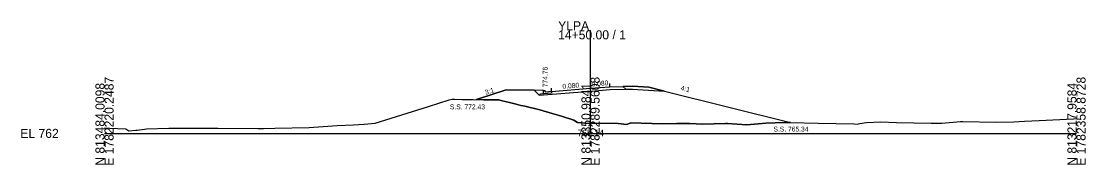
# Model space of a CAD drawing. Extents: x -76 to 1303, y -10 to 9544.
# Drawn here: x -25.7 to 302.8, y 4490.3 to 4534.7 of the extents above; entities that cross this region are included whole.
import ezdxf

# ---------------------------------------------------------------- set-up
doc = ezdxf.new("R2010")
doc.units = 0
for name, color, linetype in [('Exist Cross Section Cell', 7, 'Continuous'), ('Exist XS Center Line Elevation Label', 7, 'Continuous'), ('Exist XS Ground Line', 7, 'Continuous'), ('Prop XS Dump Level', 7, 'Continuous'), ('Prop XS Earthwork Shape', 7, 'Continuous'), ('Prop XS EOT Tick Mark', 7, 'Continuous'), ('Prop XS Finish Grade', 7, 'Continuous'), ('Prop XS Finish Grade CurbGutter', 7, 'Continuous'), ('Prop XS Finish Grade Earthwork', 7, 'Continuous'), ('Prop XS Finish Grade Paved Shoulder', 7, 'Continuous'), ('Prop XS Finish Grade Pavement', 7, 'Continuous'), ('Prop XS Hydro Elevations', 7, 'Continuous'), ('Prop XS Pvmt Edge Slope', 7, 'Continuous'), ('Prop XS SE Text', 7, 'Continuous'), ('Prop XS Side Slope Text', 7, 'Continuous'), ('Prop XS SS Elevation Text', 7, 'Continuous'), ('Prop XS Subgrade CurbGutter', 7, 'Continuous'), ('Prop XS Subgrade Earthwork', 7, 'Continuous'), ('Scratch_Level_3', 7, 'Continuous')]:
    doc.layers.add(name, color=color, linetype=linetype)

msp = doc.modelspace()

# ---------------------------------------------------------------- linework, layer by layer
at = {"layer": 'Exist Cross Section Cell'}
for p, q in [((150, 4500), (150, 4531.87)), ((0, 4500), (150, 4500)), ((150, 4500), (300, 4500))]:
    msp.add_line(p, q, dxfattribs=at)
at = {"layer": 'Exist XS Ground Line'}
for p, q in [((83.56, 4503.15), (99.98, 4508.29)), ((99.98, 4508.29), (106.4, 4510.34)), ((106.4, 4510.34), (107.28, 4510.62)), ((107.28, 4510.62), (108.01, 4510.59)), ((108.01, 4510.59), (110.34, 4510.51)), ((110.34, 4510.51), (111.4, 4510.46)), ((111.4, 4510.46), (113.79, 4510.43)), ((113.79, 4510.43), (117.1, 4510.42)), ((117.1, 4510.42), (121.68, 4510.41)), ((121.68, 4510.41), (122.76, 4510.04)), ((122.76, 4510.04), (123.61, 4509.86)), ((123.61, 4509.86), (125.37, 4509.44)), ((125.37, 4509.44), (127.06, 4509.03)), ((127.06, 4509.03), (128.45, 4508.67)), ((128.45, 4508.67), (129.7, 4508.41)), ((129.7, 4508.41), (134.36, 4507.31)), ((134.36, 4507.31), (138.19, 4506.11)), ((138.19, 4506.11), (141.05, 4505.32)), ((141.05, 4505.32), (144.8, 4504.04)), ((288.47, 4503.99), (299.1, 4504.49)), ((299.1, 4504.49), (300, 4504.57)), ((0, 4501.76), (1.49, 4501.64)), ((1.49, 4501.64), (6.55, 4501.43)), ((6.55, 4501.43), (7.5, 4500.84)), ((7.5, 4500.84), (9.69, 4500.96)), ((9.69, 4500.96), (10.1, 4500.99)), ((10.1, 4500.99), (12.3, 4501.32)), ((12.3, 4501.32), (12.99, 4501.36)), ((12.99, 4501.36), (19.89, 4501.66)), ((19.89, 4501.66), (20.56, 4501.66)), ((20.56, 4501.66), (34.98, 4501.63)), ((34.98, 4501.63), (47.37, 4501.51)), ((47.37, 4501.51), (49.07, 4501.5)), ((49.07, 4501.5), (52.52, 4501.58)), ((52.52, 4501.58), (63.12, 4501.82)), ((63.12, 4501.82), (71.85, 4502.39)), ((71.85, 4502.39), (76.8, 4502.67)), ((76.8, 4502.67), (80.16, 4502.83)), ((80.16, 4502.83), (83.56, 4503.15)), ((144.8, 4504.04), (145.96, 4503.32)), ((145.96, 4503.32), (149.33, 4503.07)), ((149.33, 4503.07), (150.28, 4503.16)), ((150.28, 4503.16), (158.49, 4503.06)), ((158.49, 4503.06), (161.17, 4502.75)), ((161.17, 4502.75), (162.4, 4503.27)), ((162.4, 4503.27), (172.16, 4502.99)), ((172.16, 4502.99), (176.6, 4503.05)), ((176.6, 4503.05), (180.58, 4503.05)), ((180.58, 4503.05), (184.63, 4502.8)), ((184.63, 4502.8), (191.64, 4503.03)), ((191.64, 4503.03), (192.27, 4503.06)), ((192.27, 4503.06), (198.26, 4502.65)), ((198.26, 4502.65), (204.12, 4503.11)), ((204.12, 4503.11), (209.84, 4503.32)), ((209.84, 4503.32), (210.87, 4503.32)), ((210.87, 4503.32), (211.7, 4503.34)), ((211.7, 4503.34), (220.26, 4503.12)), ((220.26, 4503.12), (231.31, 4502.94)), ((231.31, 4502.94), (232.26, 4502.9)), ((232.26, 4502.9), (233.15, 4503.04)), ((233.15, 4503.04), (235.13, 4503.35)), ((235.13, 4503.35), (239.63, 4503.58)), ((239.63, 4503.58), (244.4, 4503.41)), ((244.4, 4503.41), (255.16, 4503.12)), ((255.16, 4503.12), (256.57, 4503.13)), ((256.57, 4503.13), (256.97, 4503.17)), ((256.97, 4503.17), (258.43, 4503.17)), ((258.43, 4503.17), (264.2, 4503.66)), ((264.2, 4503.66), (264.94, 4503.67)), ((264.94, 4503.67), (275.13, 4503.48)), ((275.13, 4503.48), (280.66, 4503.59)), ((280.66, 4503.59), (283.93, 4503.75)), ((283.93, 4503.75), (288.47, 4503.99))]:
    msp.add_line(p, q, dxfattribs=at)
at = {"layer": 'Prop XS Dump Level'}
for p, q in [((150, 4513.96), (156, 4514.44)), ((138, 4513), (150, 4513.96))]:
    msp.add_line(p, q, dxfattribs=at)
at = {"layer": 'Prop XS Earthwork Shape'}
msp.add_lwpolyline([(172.83, 4513.07), (211.76, 4503.34), (211.7, 4503.34), (210.87, 4503.32), (209.84, 4503.32), (204.12, 4503.11), (198.26, 4502.65), (192.27, 4503.06), (191.64, 4503.03), (184.63, 4502.8), (180.58, 4503.05), (176.6, 4503.05), (172.16, 4502.99), (162.4, 4503.27), (161.17, 4502.75), (158.49, 4503.06), (150.28, 4503.16), (149.33, 4503.07), (145.96, 4503.32), (144.8, 4504.04), (141.05, 4505.32), (138.19, 4506.11), (134.36, 4507.31), (129.7, 4508.41), (128.45, 4508.67), (127.06, 4509.03), (125.37, 4509.44), (123.61, 4509.86), (122.76, 4510.04), (121.68, 4510.41), (117.1, 4510.42), (114.77, 4510.43), (124, 4513.5), (132.61, 4513.32), (134.16, 4511.78), (150.07, 4513.05), (156.05, 4513.53), (160.9, 4513.62), (162.98, 4513.67)], close=True, dxfattribs=at)
at = {"layer": 'Prop XS EOT Tick Mark'}
for p, q in [((156, 4514.44), (156, 4515.44)), ((138, 4513), (138, 4514))]:
    msp.add_line(p, q, dxfattribs=at)
at = {"layer": 'Prop XS Finish Grade'}
for p, q in [((160, 4514.52), (163, 4514.58)), ((163, 4514.58), (168, 4514.28)), ((168, 4514.28), (172.83, 4513.07)), ((135.5, 4513.26), (132.61, 4513.32))]:
    msp.add_line(p, q, dxfattribs=at)
at = {"layer": 'Prop XS Finish Grade CurbGutter'}
for p, q in [((135.5, 4513.26), (135.75, 4513.26)), ((135.75, 4513.26), (135.88, 4513.25)), ((135.97, 4513.16), (135.88, 4513.25)), ((136.03, 4512.91), (135.97, 4513.16)), ((136.13, 4512.82), (136.03, 4512.91)), ((136.25, 4512.79), (136.13, 4512.82)), ((138, 4513), (136.25, 4512.79))]:
    msp.add_line(p, q, dxfattribs=at)
at = {"layer": 'Prop XS Finish Grade Earthwork'}
for p, q in [((124, 4513.5), (114.77, 4510.43)), ((132.61, 4513.32), (124, 4513.5)), ((172.83, 4513.07), (211.76, 4503.34))]:
    msp.add_line(p, q, dxfattribs=at)
at = {"layer": 'Prop XS Finish Grade Paved Shoulder'}
msp.add_line((156, 4514.44), (160, 4514.52), dxfattribs=at)
at = {"layer": 'Prop XS Finish Grade Pavement'}
for p, q in [((150, 4513.96), (156, 4514.44)), ((138, 4513), (150, 4513.96))]:
    msp.add_line(p, q, dxfattribs=at)
at = {"layer": 'Prop XS Pvmt Edge Slope'}
for p, q in [((160, 4514.52), (160.9, 4513.62)), ((134.5, 4512.14), (134.16, 4511.78)), ((135.5, 4512.22), (134.5, 4512.14))]:
    msp.add_line(p, q, dxfattribs=at)
at = {"layer": 'Prop XS Subgrade CurbGutter'}
for p, q in [((135.5, 4512.22), (135.5, 4513.26)), ((138, 4512.42), (135.5, 4512.22)), ((138, 4513), (138, 4512.42))]:
    msp.add_line(p, q, dxfattribs=at)
at = {"layer": 'Prop XS Subgrade Earthwork'}
for p, q in [((134.16, 4511.78), (132.61, 4513.32)), ((134.16, 4511.78), (150.07, 4513.05)), ((150.07, 4513.05), (156.05, 4513.53)), ((156.05, 4513.53), (160.9, 4513.62)), ((160.9, 4513.62), (162.98, 4513.67)), ((162.98, 4513.67), (172.83, 4513.07))]:
    msp.add_line(p, q, dxfattribs=at)
at = {"layer": 'Scratch_Level_3'}
for p, q in [((163, 4514.58), (160, 4514.52)), ((160, 4514.52), (160.9, 4513.62)), ((168, 4514.28), (163, 4514.58)), ((172.83, 4513.07), (168, 4514.28)), ((160.9, 4513.62), (162.98, 4513.67)), ((162.98, 4513.67), (172.83, 4513.07))]:
    msp.add_line(p, q, dxfattribs=at)

# ---------------------------------------------------------------- texts
at = {"layer": 'Exist Cross Section Cell'}
for s, p in [('YLPA', (140, 4531.87)), ('14+50.00 / 1', (140, 4529.07)), ('EL 762', (-26, 4498.6))]:
    msp.add_text(s, height=2.8, dxfattribs=at).set_placement(p)
for s, p in [('N 813484.0098', (0, 4490)), ('E 1782220.2487', (2.8, 4490)), ('N 813350.9841', (150, 4490)), ('E 1782289.5608', (152.8, 4490)), ('N 813217.9584', (300, 4490)), ('E 1782358.8728', (302.8, 4490))]:
    msp.add_text(s, height=2.8, rotation=90, dxfattribs=at).set_placement(p)
at = {"layer": 'Exist XS Center Line Elevation Label'}
msp.add_text('765.14', height=2, dxfattribs=at).set_placement((145.96, 4499.14))
at = {"layer": 'Prop XS Dump Level'}
msp.add_text('Case4', height=0.04, dxfattribs=at).set_placement((168, 4514.24))
at = {"layer": 'Prop XS Hydro Elevations'}
msp.add_text('774.76', height=1.5, rotation=90, dxfattribs=at).set_placement((136.75, 4514.26))
at = {"layer": 'Prop XS SE Text'}
for p in [(141.38, 4513.77), (150.38, 4514.49)]:
    msp.add_text('0.080', height=1.5, rotation=4.5739, dxfattribs=at).set_placement(p)
at = {"layer": 'Prop XS Side Slope Text'}
for s, rotation, p in [('4:1', 345.9638, (177.7, 4513.4)), ('3:1', 17.8228, (117.66, 4511.89))]:
    msp.add_text(s, height=1.5, rotation=rotation, dxfattribs=at).set_placement(p)
at = {"layer": 'Prop XS SS Elevation Text'}
for s, p in [('S.S. 772.43', (106.6, 4507.45)), ('S.S. 765.34', (206.46, 4500.58))]:
    msp.add_text(s, height=1.5, dxfattribs=at).set_placement(p)

doc.saveas('drawing.dxf')
